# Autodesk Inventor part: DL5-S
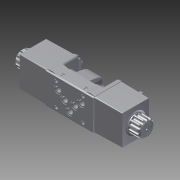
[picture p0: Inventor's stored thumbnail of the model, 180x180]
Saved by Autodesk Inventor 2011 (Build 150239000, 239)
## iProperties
Created: 2012-01
Part Number: DL5-S
Document SubType Name: Modeling
Designer: khramov
Density: 1 g/cm^3
Author: khramov
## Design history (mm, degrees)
derived "DL5_S1_10N_D24K1.iam"
node "Твердое тело1"
node "0210566_0144453.ipt:1"
node "026986.ipt:1"
node "0119412.ipt:1"
node "190315.ipt:1"
node "026986.ipt:2"
node "0119412.ipt:2"
node "190315.ipt:2"
sketch "3001630001ON.ipt:1"
sketch "0530779_DIN7985.ipt:1"
sketch "0530779_DIN7985.ipt:2"
